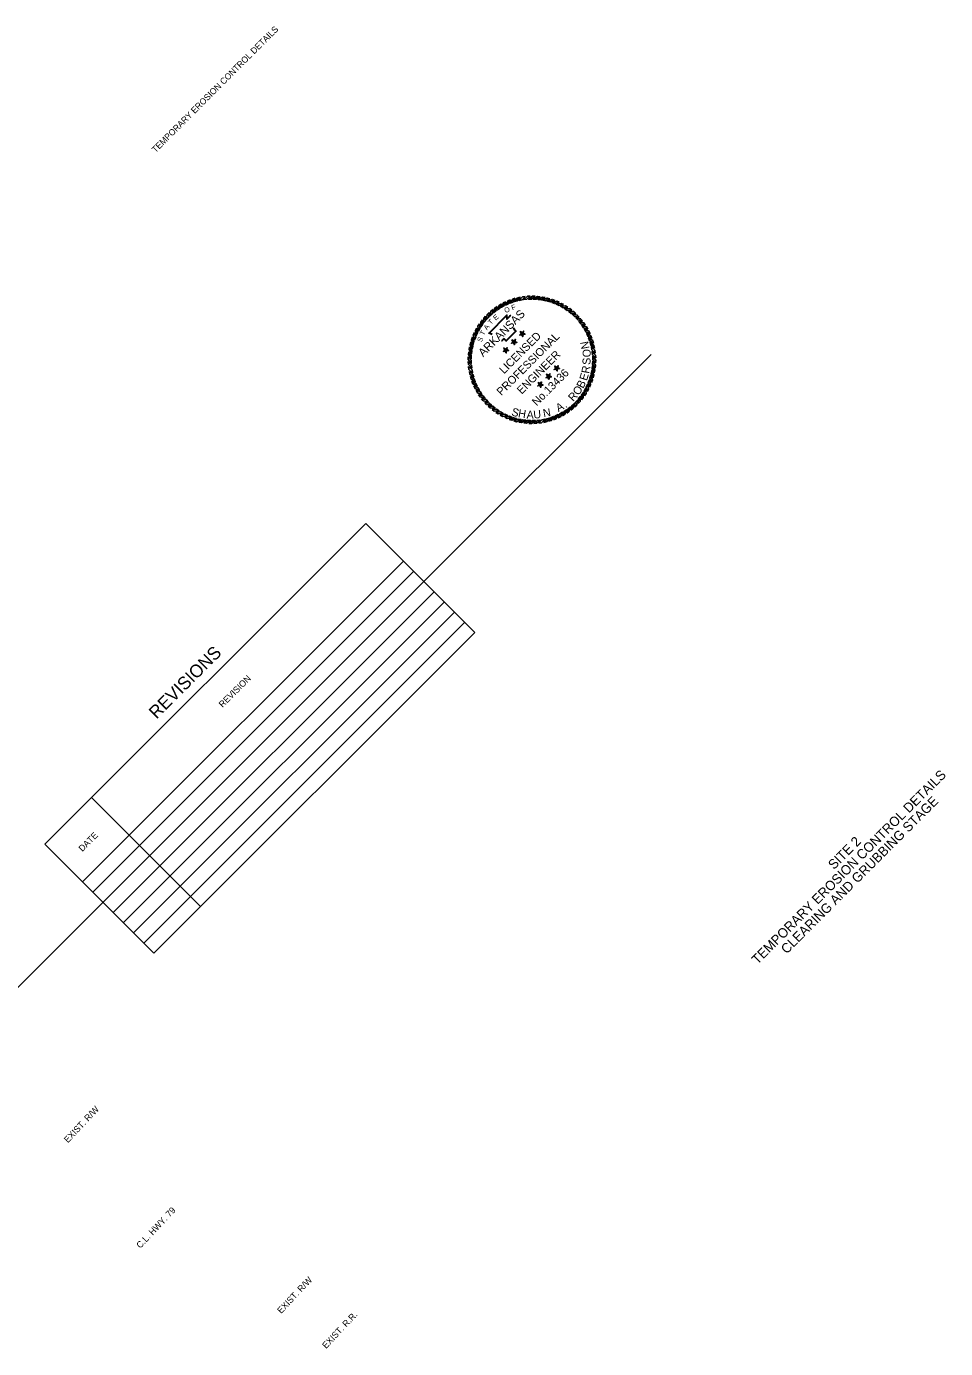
# Model space of a CAD drawing. Extents: x 1388120 to 1389841, y 1944307 to 1945760.
# Drawn here: x 1388980 to 1389841, y 1944521 to 1945760 of the extents above; entities that cross this region are included whole.
import ezdxf

# ---------------------------------------------------------------- set-up
doc = ezdxf.new("R2010")
doc.units = 0
for name, color, linetype in [('1', 7, 'Continuous'), ('60', 7, 'Continuous'), ('Default', 7, 'Continuous'), ('G-ANNO-SYMB', 7, 'Continuous'), ('R_Draft', 7, 'Continuous')]:
    doc.layers.add(name, color=color, linetype=linetype)

msp = doc.modelspace()

# ---------------------------------------------------------------- linework, layer by layer
at = {"layer": '1'}
for p, q in [((1389352.4, 1945239.6), (1389565.3, 1945452.4)), ((1388849.6, 1944736.7), (1389051.9, 1944939.1))]:
    msp.add_line(p, q, dxfattribs=at)
at = {"layer": 'Default'}
for p, q in [((1388997.5, 1944993.5), (1389298, 1945294)), ((1389298, 1945294), (1389400.2, 1945191.9)), ((1389032.8, 1944958.2), (1389333.4, 1945258.7)), ((1389042.4, 1944948.6), (1389342.9, 1945249.1)), ((1389051.9, 1944939.1), (1389352.4, 1945239.6)), ((1389061.5, 1944929.5), (1389362, 1945230.1)), ((1389061.5, 1944929.5), (1389362, 1945230.1)), ((1389071, 1944920), (1389371.5, 1945220.5)), ((1389080.6, 1944910.4), (1389381.1, 1945211)), ((1389090.1, 1944900.9), (1389390.6, 1945201.4)), ((1389099.7, 1944891.4), (1389400.2, 1945191.9)), ((1389041.2, 1945037.2), (1389143.4, 1944935.1)), ((1388997.5, 1944993.5), (1389099.7, 1944891.4))]:
    msp.add_line(p, q, dxfattribs=at)
at = {"layer": 'G-ANNO-SYMB'}
for points in [[(1389429.3, 1945501.9), (1389427, 1945500.8), (1389425.1, 1945496.7), (1389427.5, 1945498)], [(1389433.7, 1945503.7), (1389431.3, 1945502.7), (1389429, 1945498.8), (1389431.5, 1945499.9)], [(1389438.1, 1945505.1), (1389435.7, 1945504.3), (1389433.1, 1945500.5), (1389435.7, 1945501.5)], [(1389442.7, 1945506.1), (1389440.2, 1945505.6), (1389437.3, 1945502), (1389440, 1945502.7)], [(1389447.3, 1945506.8), (1389444.8, 1945506.4), (1389441.7, 1945503.1), (1389444.4, 1945503.6)], [(1389452, 1945507.1), (1389449.4, 1945507), (1389446.1, 1945503.9), (1389448.8, 1945504.2)], [(1389456.7, 1945507), (1389454.1, 1945507.1), (1389450.5, 1945504.3), (1389453.3, 1945504.4)], [(1389461.4, 1945506.6), (1389458.8, 1945506.9), (1389455, 1945504.4), (1389457.8, 1945504.2)], [(1389466, 1945505.8), (1389463.5, 1945506.3), (1389459.5, 1945504.1), (1389462.2, 1945503.8)], [(1389470.5, 1945504.7), (1389468, 1945505.4), (1389463.9, 1945503.5), (1389466.6, 1945502.9)], [(1389475, 1945503.2), (1389472.5, 1945504.1), (1389468.2, 1945502.5), (1389470.9, 1945501.7)], [(1389479.3, 1945501.4), (1389476.9, 1945502.4), (1389472.5, 1945501.2), (1389475.1, 1945500.2)], [(1389410.3, 1945488.4), (1389408.6, 1945486.5), (1389408.4, 1945482), (1389410.2, 1945484.1)], [(1389413.7, 1945491.7), (1389411.8, 1945489.9), (1389411.3, 1945485.4), (1389413.2, 1945487.4)], [(1389417.3, 1945494.7), (1389415.3, 1945493.1), (1389414.4, 1945488.6), (1389416.4, 1945490.5)], [(1389421.1, 1945497.4), (1389419, 1945496), (1389417.7, 1945491.6), (1389419.9, 1945493.3)], [(1389425.1, 1945499.8), (1389422.9, 1945498.5), (1389421.3, 1945494.3), (1389423.6, 1945495.8)], [(1389483.4, 1945499.2), (1389481.2, 1945500.4), (1389476.7, 1945499.6), (1389479.2, 1945498.4)], [(1389487.4, 1945496.7), (1389485.2, 1945498.1), (1389480.7, 1945497.6), (1389483.1, 1945496.2)], [(1389491.1, 1945493.9), (1389489.1, 1945495.5), (1389484.5, 1945495.3), (1389486.8, 1945493.8)], [(1389494.7, 1945490.8), (1389492.8, 1945492.6), (1389488.2, 1945492.8), (1389490.4, 1945491)], [(1389498, 1945487.5), (1389496.2, 1945489.4), (1389491.7, 1945489.9), (1389493.7, 1945488)], [(1389402, 1945477.2), (1389400.7, 1945474.9), (1389401.6, 1945470.4), (1389402.8, 1945472.9)], [(1389404.5, 1945481.1), (1389403.1, 1945479), (1389403.6, 1945474.4), (1389405, 1945476.9)], [(1389407.3, 1945484.9), (1389405.7, 1945482.9), (1389405.9, 1945478.3), (1389407.4, 1945480.6)], [(1389501, 1945483.9), (1389499.3, 1945485.9), (1389494.9, 1945486.8), (1389496.7, 1945484.8)], [(1389503.7, 1945480.1), (1389502.2, 1945482.2), (1389497.8, 1945483.5), (1389499.5, 1945481.3)], [(1389506.1, 1945476.1), (1389504.8, 1945478.3), (1389500.5, 1945479.9), (1389502, 1945477.6)], [(1389508.2, 1945471.9), (1389507.1, 1945474.2), (1389502.9, 1945476.1), (1389504.3, 1945473.7)], [(1389396.5, 1945464.3), (1389395.8, 1945461.8), (1389397.7, 1945457.6), (1389398.3, 1945460.3)], [(1389398, 1945468.7), (1389397.1, 1945466.3), (1389398.7, 1945462), (1389399.4, 1945464.7)], [(1389399.8, 1945473), (1389398.8, 1945470.7), (1389400, 1945466.3), (1389401, 1945468.9)], [(1389436.9, 1945464.3), (1389435.9, 1945464.4), (1389434.5, 1945463), (1389436.4, 1945463.3)], [(1389436.9, 1945464.3), (1389436.8, 1945465.3), (1389435, 1945466.2), (1389435.9, 1945464.4)], [(1389436.9, 1945464.3), (1389436.4, 1945463.3), (1389437.3, 1945461.6), (1389437.7, 1945463.5)], [(1389436.9, 1945464.3), (1389437.8, 1945464.7), (1389438.2, 1945466.7), (1389436.8, 1945465.3)], [(1389436.9, 1945464.3), (1389437.7, 1945463.5), (1389439.6, 1945463.8), (1389437.8, 1945464.7)], [(1389444.6, 1945472), (1389443.6, 1945472.1), (1389442.2, 1945470.7), (1389444.2, 1945471)], [(1389444.6, 1945472), (1389444.5, 1945473), (1389442.7, 1945473.9), (1389443.6, 1945472.1)], [(1389444.6, 1945472), (1389444.2, 1945471), (1389445.1, 1945469.3), (1389445.4, 1945471.2)], [(1389444.6, 1945472), (1389445.6, 1945472.4), (1389445.9, 1945474.4), (1389444.5, 1945473)], [(1389444.6, 1945472), (1389445.4, 1945471.2), (1389447.3, 1945471.5), (1389445.6, 1945472.4)], [(1389509.9, 1945467.5), (1389509, 1945469.9), (1389505, 1945472.2), (1389506.2, 1945469.6)], [(1389511.3, 1945463), (1389510.6, 1945465.5), (1389506.8, 1945468.1), (1389507.7, 1945465.5)], [(1389512.3, 1945458.5), (1389511.8, 1945461), (1389508.2, 1945463.8), (1389509, 1945461.2)], [(1389394.5, 1945455.1), (1389394.3, 1945452.6), (1389396.8, 1945448.7), (1389396.9, 1945451.5)], [(1389395.3, 1945459.7), (1389394.9, 1945457.2), (1389397.1, 1945453.2), (1389397.4, 1945456)], [(1389429.2, 1945456.5), (1389428.2, 1945456.7), (1389426.8, 1945455.3), (1389428.7, 1945455.6)], [(1389429.2, 1945456.5), (1389429, 1945457.6), (1389427.3, 1945458.5), (1389428.2, 1945456.7)], [(1389429.2, 1945456.5), (1389428.7, 1945455.6), (1389429.6, 1945453.9), (1389429.9, 1945455.8)], [(1389429.2, 1945456.5), (1389430.1, 1945457), (1389430.4, 1945459), (1389429, 1945457.6)], [(1389429.2, 1945456.5), (1389429.9, 1945455.8), (1389431.9, 1945456.1), (1389430.1, 1945457)], [(1389513, 1945453.8), (1389512.7, 1945456.4), (1389509.4, 1945459.5), (1389509.9, 1945456.8)], [(1389513.4, 1945449.2), (1389513.2, 1945451.7), (1389510.1, 1945455.1), (1389510.4, 1945452.3)], [(1389394.1, 1945450.4), (1389394.1, 1945447.9), (1389396.9, 1945444.3), (1389396.8, 1945447)], [(1389394.1, 1945445.8), (1389394.2, 1945443.2), (1389397.3, 1945439.8), (1389397, 1945442.6)], [(1389394.4, 1945441.1), (1389394.7, 1945438.5), (1389398.1, 1945435.4), (1389397.6, 1945438.1)], [(1389476.9, 1945439.7), (1389475.9, 1945439.8), (1389474.5, 1945438.4), (1389476.5, 1945438.7)], [(1389476.9, 1945439.7), (1389476.8, 1945440.7), (1389475, 1945441.6), (1389475.9, 1945439.8)], [(1389476.9, 1945439.7), (1389476.5, 1945438.7), (1389477.4, 1945437), (1389477.7, 1945438.9)], [(1389476.9, 1945439.7), (1389477.9, 1945440.1), (1389478.2, 1945442.1), (1389476.8, 1945440.7)], [(1389476.9, 1945439.7), (1389477.7, 1945438.9), (1389479.6, 1945439.2), (1389477.9, 1945440.1)], [(1389512.1, 1945435.2), (1389512.6, 1945437.7), (1389510.4, 1945441.7), (1389510, 1945439)], [(1389512.9, 1945439.8), (1389513.2, 1945442.4), (1389510.6, 1945446.2), (1389510.5, 1945443.4)], [(1389513.3, 1945444.5), (1389513.4, 1945447), (1389510.6, 1945450.7), (1389510.6, 1945447.9)], [(1389395.1, 1945436.4), (1389395.6, 1945433.9), (1389399.2, 1945431.1), (1389398.5, 1945433.8)], [(1389396.1, 1945431.9), (1389396.8, 1945429.4), (1389400.6, 1945426.9), (1389399.7, 1945429.5)], [(1389397.5, 1945427.4), (1389398.4, 1945425), (1389402.4, 1945422.8), (1389401.3, 1945425.3)], [(1389461.5, 1945424.2), (1389462.4, 1945424.7), (1389462.7, 1945426.7), (1389461.3, 1945425.3)], [(1389469.2, 1945432), (1389468.2, 1945432.1), (1389466.8, 1945430.7), (1389468.7, 1945431)], [(1389469.2, 1945432), (1389469.1, 1945433), (1389467.3, 1945433.9), (1389468.2, 1945432.1)], [(1389469.2, 1945432), (1389468.7, 1945431), (1389469.6, 1945429.3), (1389470, 1945431.2)], [(1389469.2, 1945432), (1389470.1, 1945432.4), (1389470.5, 1945434.4), (1389469.1, 1945433)], [(1389469.2, 1945432), (1389470, 1945431.2), (1389471.9, 1945431.5), (1389470.1, 1945432.4)], [(1389507.6, 1945421.9), (1389508.7, 1945424.2), (1389507.5, 1945428.7), (1389506.5, 1945426.1)], [(1389509.5, 1945426.2), (1389510.3, 1945428.6), (1389508.8, 1945432.9), (1389508, 1945430.3)], [(1389511, 1945430.7), (1389511.6, 1945433.1), (1389509.7, 1945437.3), (1389509.2, 1945434.6)], [(1389399.3, 1945423.1), (1389400.4, 1945420.7), (1389404.5, 1945418.8), (1389403.2, 1945421.2)], [(1389401.4, 1945418.9), (1389402.6, 1945416.6), (1389406.9, 1945415), (1389405.4, 1945417.4)], [(1389403.8, 1945414.8), (1389405.2, 1945412.7), (1389409.6, 1945411.5), (1389407.9, 1945413.7)], [(1389461.5, 1945424.2), (1389460.5, 1945424.4), (1389459.1, 1945423), (1389461, 1945423.3)], [(1389461.5, 1945424.2), (1389461.3, 1945425.3), (1389459.6, 1945426.2), (1389460.5, 1945424.4)], [(1389461.5, 1945424.2), (1389461, 1945423.3), (1389461.9, 1945421.6), (1389462.2, 1945423.5)], [(1389461.5, 1945424.2), (1389462.2, 1945423.5), (1389464.2, 1945423.8), (1389462.4, 1945424.7)], [(1389500.2, 1945410), (1389501.7, 1945412.1), (1389501.6, 1945416.6), (1389500, 1945414.3)], [(1389503, 1945413.8), (1389504.4, 1945415.9), (1389503.8, 1945420.5), (1389502.5, 1945418.1)], [(1389505.5, 1945417.8), (1389506.7, 1945420), (1389505.8, 1945424.5), (1389504.6, 1945422)], [(1389406.5, 1945411), (1389408.1, 1945409), (1389412.6, 1945408.1), (1389410.7, 1945410.2)], [(1389409.5, 1945407.4), (1389411.2, 1945405.6), (1389415.8, 1945405), (1389413.8, 1945406.9)], [(1389412.8, 1945404.1), (1389414.7, 1945402.4), (1389419.2, 1945402.2), (1389417.1, 1945403.9)], [(1389486.3, 1945397.5), (1389488.4, 1945399), (1389489.7, 1945403.3), (1389487.5, 1945401.6)], [(1389490.1, 1945400.2), (1389492.1, 1945401.8), (1389493.1, 1945406.3), (1389491, 1945404.4)], [(1389493.7, 1945403.2), (1389495.6, 1945405), (1389496.2, 1945409.5), (1389494.3, 1945407.5)], [(1389497.1, 1945406.5), (1389498.8, 1945408.4), (1389499, 1945413), (1389497.3, 1945410.8)], [(1389416.3, 1945401), (1389418.3, 1945399.4), (1389422.9, 1945399.6), (1389420.6, 1945401.2)], [(1389420, 1945398.2), (1389422.2, 1945396.8), (1389426.7, 1945397.3), (1389424.3, 1945398.7)], [(1389424, 1945395.7), (1389426.3, 1945394.5), (1389430.8, 1945395.4), (1389428.2, 1945396.5)], [(1389428.2, 1945393.6), (1389430.5, 1945392.5), (1389434.9, 1945393.7), (1389432.3, 1945394.7)], [(1389432.5, 1945391.7), (1389434.9, 1945390.9), (1389439.2, 1945392.4), (1389436.5, 1945393.2)], [(1389436.9, 1945390.2), (1389439.4, 1945389.5), (1389443.5, 1945391.4), (1389440.8, 1945392)], [(1389441.5, 1945389.1), (1389444, 1945388.6), (1389448, 1945390.8), (1389445.2, 1945391.2)], [(1389446.1, 1945388.3), (1389448.6, 1945388), (1389452.4, 1945390.5), (1389449.7, 1945390.7)], [(1389450.7, 1945387.9), (1389453.3, 1945387.8), (1389456.9, 1945390.6), (1389454.1, 1945390.5)], [(1389455.4, 1945387.8), (1389458, 1945388), (1389461.4, 1945391), (1389458.6, 1945390.7)], [(1389460.1, 1945388.1), (1389462.6, 1945388.5), (1389465.8, 1945391.8), (1389463, 1945391.3)], [(1389464.7, 1945388.8), (1389467.2, 1945389.4), (1389470.1, 1945392.9), (1389467.4, 1945392.2)], [(1389469.3, 1945389.9), (1389471.8, 1945390.6), (1389474.3, 1945394.4), (1389471.7, 1945393.4)], [(1389473.8, 1945391.3), (1389476.2, 1945392.2), (1389478.4, 1945396.2), (1389475.9, 1945395)], [(1389478.1, 1945393), (1389480.4, 1945394.1), (1389482.4, 1945398.3), (1389479.9, 1945396.9)], [(1389482.3, 1945395.1), (1389484.5, 1945396.4), (1389486.1, 1945400.7), (1389483.8, 1945399.1)]]:
    msp.add_lwpolyline(points, close=True, dxfattribs=at)
for points in [[(1389416.3, 1945471.3), (1389413.2, 1945472.5), (1389430.2, 1945489.5), (1389430.6, 1945486.3), (1389431.7, 1945487.5), (1389432.7, 1945488.4), (1389433.8, 1945489.3)], [(1389416.5, 1945471.7), (1389413.9, 1945472.6), (1389429.9, 1945488.7), (1389430.3, 1945485.4), (1389432, 1945487.2), (1389432.9, 1945488.2), (1389434, 1945489)], [(1389436.8, 1945477.5), (1389436.8, 1945477), (1389437, 1945476.6), (1389437.8, 1945475.6), (1389439, 1945474.4), (1389429.5, 1945464.9), (1389427.9, 1945466.5), (1389427.5, 1945466.9), (1389427, 1945466.6), (1389425.7, 1945465.2), (1389425.1, 1945465.4)], [(1389436.4, 1945477.6), (1389436.4, 1945476.9), (1389436.7, 1945476.4), (1389437.5, 1945475.3), (1389438.4, 1945474.4), (1389429.5, 1945465.5), (1389428.2, 1945466.8), (1389427.6, 1945467.3), (1389426.8, 1945466.9), (1389425.6, 1945465.6), (1389425.2, 1945465.7)]]:
    msp.add_lwpolyline(points, dxfattribs=at)

# ---------------------------------------------------------------- texts
at = {"layer": '1'}
msp.add_text('TEMPORARY EROSION CONTROL DETAILS', height=5.862, rotation=45, dxfattribs=at).set_placement((1389101.2, 1945641.1))
at = {"layer": '60'}
for s, p in [('TEMPORARY EROSION CONTROL DETAILS', (1389665, 1944880.4)), ('CLEARING AND GRUBBING STAGE', (1389692.3, 1944890.2)), ('SITE 2', (1389736.5, 1944969.3))]:
    msp.add_text(s, height=9, rotation=45, dxfattribs=at).set_placement(p)
at = {"layer": 'Default'}
for s, height, p in [('REVISIONS', 12, (1389102.1, 1945110.2)), ('REVISION', 6, (1389164, 1945121.2)), ('DATE', 6, (1389032.6, 1944986.2))]:
    msp.add_text(s, height=height, rotation=45, dxfattribs=at).set_placement(p)
at = {"layer": 'G-ANNO-SYMB'}
for s, height, rotation, p in [('ARKANSAS', 7.75, 45, (1389408, 1945449.9)), ('E', 4.75, 41.672, (1389419.8, 1945484.1)), ('O', 4.75, 26.2218, (1389429.1, 1945491.1)), ('F', 4.75, 20.3628, (1389435.4, 1945493.8)), ('A', 4.75, 53.6788, (1389411.7, 1945474.9)), ('T', 4.75, 46.4789, (1389415.4, 1945479.9)), ('S', 4.75, 64.7726, (1389406.4, 1945463.6)), ('T', 4.75, 61.9015, (1389408.7, 1945469.8)), ('PROFESSIONAL', 7.5, 45, (1389425.1, 1945413.5)), ('LICENSED', 7.5, 45, (1389427.5, 1945433.7)), ('N', 7.5, 101.1007, (1389507.6, 1945458.3)), ('ENGINEER', 7.5, 45, (1389444, 1945414.7)), ('O', 7.5, 89.7757, (1389508.7, 1945449.8)), ('No.13436', 7.47, 45, (1389458.3, 1945403.8)), ('R', 7.5, 80.6597, (1389507.3, 1945434.2)), ('S', 7.5, 88.4878, (1389508.5, 1945442.7)), ('B', 7.5, 63.885, (1389501.7, 1945420.1)), ('E', 7.5, 72.8315, (1389505.1, 1945427.4)), ('R', 7.5, 48.2287, (1389492.4, 1945407.9)), ('O', 7.5, 56.4296, (1389497.5, 1945413.6)), ('S', 7.5, 343.1636, (1389433.9, 1945395.6)), ('N', 7.5, 9.9326, (1389464.7, 1945393.7)), ('A', 7.5, 28.0991, (1389478.5, 1945398.4)), ('.', 7.5, 36.3, (1389485.3, 1945402)), ('H', 7.5, 350.619, (1389440.4, 1945393.9)), ('A', 7.5, 358.4472, (1389448.6, 1945392.4)), ('U', 7.5, 5.9026, (1389455.4, 1945392.3))]:
    msp.add_text(s, height=height, rotation=rotation, dxfattribs=at).set_placement(p)
at = {"layer": 'R_Draft'}
for s, rotation, p in [('EXIST. R/W', 46.6607, (1389019.1, 1944713.3)), ('C.L. HWY. 79', 46.736, (1389086.9, 1944614.4)), ('EXIST. R/W', 46.6607, (1389218.8, 1944553.3)), ('EXIST. R.R.', 46.6607, (1389260.9, 1944520.5))]:
    msp.add_text(s, height=6, rotation=rotation, dxfattribs=at).set_placement(p)

doc.saveas('drawing.dxf')
